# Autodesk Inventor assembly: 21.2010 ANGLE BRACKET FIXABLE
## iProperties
Created: 2007-01
Part Number: 21.2010 ANGLE BRACKET FIXABLE
Document SubType Name: Assembly
Designer: Andy Moles
Author: Andy Moles
